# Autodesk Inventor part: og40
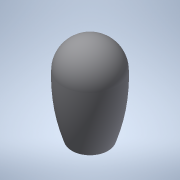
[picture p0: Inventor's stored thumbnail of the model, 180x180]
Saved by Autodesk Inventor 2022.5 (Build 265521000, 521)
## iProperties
Created: 2016-12
Part Number: og40
Material: 一般
Document SubType Name: Modeling
Designer: imaocorp
Density: 1 g/cm^3
Appearance: 既定
Author: imaocorp
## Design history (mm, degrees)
node "og40.x_t1"
node "og40"
node "Base1"
